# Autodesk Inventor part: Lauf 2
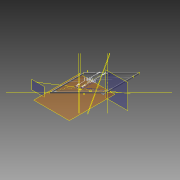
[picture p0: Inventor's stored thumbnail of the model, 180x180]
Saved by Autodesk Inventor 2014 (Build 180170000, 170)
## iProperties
Created: 2013-09
Part Number: Lauf 2
Material: Edelstahl
Document SubType Name: Modeling
Designer: Stefan Tammegger
Mass: 19399.1 g
Surface Area: 21755.4 cm^2
Volume: 2400.88 cm^3
Density: 8.08 g/cm^3
Appearance: Halbpoliert
Author: Stefan Tammegger
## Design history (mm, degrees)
node "Blöcke"
  sketch "FR 50 30 2"
    geometry: L1 (-39.377, 51.937)-(-65.377, 51.937); L2 (-67.377, 53.937)-(-67.377, 99.937); L3 (-65.377, 101.937)-(-39.377, 101.937); L4 (-37.377, 99.937)-(-37.377, 53.937); L5 (-39.377, 53.937)-(-65.377, 53.937); L6 (-65.377, 53.937)-(-65.377, 99.937); L7 (-65.377, 99.937)-(-39.377, 99.937); L8 (-39.377, 99.937)-(-39.377, 53.937); A1 r 2 centre (-39.377, 53.937) between (-39.377, 51.937) and (-37.377, 53.937); A2 r 2 centre (-39.377, 99.937) between (-37.377, 99.937) and (-39.377, 101.937); A3 r 2 centre (-65.377, 99.937) between (-65.377, 101.937) and (-67.377, 99.937); A4 r 2 centre (-65.377, 53.937) between (-67.377, 53.937) and (-65.377, 51.937); 4 further points
    constraints: 16 end point, 8 point on circle, 8 tangent, 6 point on line, 4 centre point, 4 parallel, 3 equal radius, 2 perpendicular, 1 horizontal, 1 midpoint, 3 other
    dimensions: "d1" = 30 distance of point (-67.377, 101.937) point (-37.377, 101.937); "d2" = 50 distance of point (-67.377, 51.937) point (-67.377, 101.937); "d3" = 2 distance between parallel lines of L2 L6; "d4" = 2 radius of A1
workplane "Arbeitsebene1"
sketch "Skizze1"
  geometry: L1 (-623.284, -302.67)-(-678.284, -302.67) reference; L2 (-678.284, -302.67)-(-678.284, -477.67) reference; L3 (501.716, 567.33)-(318.716, 567.33) reference; L4 (318.716, 567.33)-(318.716, 397.33) reference; L5 (-233.284, 47.33)-(-483.284, 47.33) reference; L6 (-483.284, 47.33)-(-483.284, -127.67) reference; L7 (318.716, 567.33)-(-483.284, 47.33); L8 (-358.284, 128.377)-(-358.284, 1168.377); 2 further points
  constraints: 4 end point, 1 coincident, 1 parallel, 1 point on line
  dimensions: "d0" = 1040 distance of L8.start L8.end
  node "Referenz1"
  node "Referenz2"
  node "Referenz3"
  node "Referenz4"
  node "Referenz5"
  node "Referenz6"
workplane "Arbeitsebene2"
  workpoint "Arbeitspunkt1"
  workaxis "Arbeitsachse1"
workpoint "Arbeitspunkt2"
workplane "Arbeitsebene3"
  workaxis "Arbeitsachse2"
  workpoint "Arbeitspunkt3"
sketch "Skizze4"
  geometry: 2 further points
  dimensions: "d12" = 20 dimension on point (140.706, 0)
extrude "Extrusion3" new body sketch "Skizze4" stored distance "d13" = 3000; taper "d14" = 0 deg
workplane "Arbeitsebene4"
sketch "Skizze5"
  geometry: L1 (-113.304, 75.845)-(-131.627, 75.845) reference; L2 (287.902, -17.155)-(287.902, 28.845) reference; 1 further point
  constraints: 1 horizontal, 1 vertical
extrude "Extrusion4" new body sketch "Skizze5" stored distance "d15" = 4000; taper "d16" = 0 deg
workplane "Arbeitsebene5"
sketch "Skizze6"
  geometry: L1 (-97, 0)-(-97, -165) reference; 1 further point
  dimensions: "d17" = 30 dimension on L1
extrude "Extrusion5" new body sketch "Skizze6" stored distance "d18" = 4000; taper "d19" = 0 deg
workplane "Arbeitsebene6"
feature "Trennen1"
workplane "Arbeitsebene7"
workplane "Arbeitsebene8"
feature "Trennen5"
feature "Trennen6"
workplane "Arbeitsebene9"
feature "Trennen7"
feature "Trennen8"
workplane "Arbeitsebene10"
sketch "Skizze7"
  geometry: L1 (318.716, 397.33)-(41.716, 397.33) reference; L2 (41.716, 397.33)-(41.716, 222.33) reference; L3 (41.716, 222.33)-(-233.284, 222.33) reference; L4 (-233.284, 222.33)-(-233.284, 47.33) reference; L5 (-233.284, 47.33)-(-483.284, 47.33) reference; L6 (-483.284, 47.33)-(-483.284, -127.67) reference; L7 (-483.284, -127.67)-(-623.284, -127.67) reference; L8 (-623.284, -127.67)-(-623.284, -302.67) reference; L9 (-623.284, -302.67)-(-678.284, -302.67) reference; L10 (-678.284, -302.67)-(-678.284, -477.67) reference; L11 (-678.284, -477.67)-(-733.284, -477.67) reference; L12 (318.716, 567.33)-(318.716, 397.33) reference; L13 (-233.284, 222.33)-(-233.284, 1262.33); 2 further points
  constraints: 2 end point, 1 coincident, 1 parallel
  dimensions: "d20" = 1040 distance of L3.end L13.end
  node "Referenz10"
  node "Referenz11"
  node "Referenz12"
  node "Referenz13"
  node "Referenz14"
  node "Referenz15"
  node "Referenz16"
  node "Referenz17"
  node "Referenz18"
  node "Referenz19"
  node "Referenz20"
  node "Referenz21"
workplane "Arbeitsebene11"
  workpoint "Arbeitspunkt4"
sketch "Skizze8"
  geometry: L1 (590.632, 60)-(-1024.704, 60) reference; 2 further points
  constraints: 1 horizontal
  dimensions: "d21" = 0 dimension on point (0, 0)
extrude "Extrusion7" new body sketch "Skizze8" stored distance "d24" = 4000; taper "d25" = 0 deg
workplane "Arbeitsebene12"
feature "Trennen9"
feature "Trennen10"
workplane "Arbeitsebene13"
feature "Trennen11"
feature "Trennen12"
sketch "Skizze9"
  geometry: L1 (0, 1478.165)-(0, 0) reference; L2 (2, 1478.997)-(2, -4.806) reference; L3 (2, 1478.997)-(2, -4.806) reference; L4 (-28, 1466.512)-(-28, 67.28) reference; L5 (-28, 1466.512)-(-28, 67.28) reference; L6 (0, 235.47)-(-80, 235.47); L7 (-80, 235.47)-(-80, 115.47); L8 (-80, 115.47)-(0, 115.47); L9 (0, 115.47)-(0, 235.47); L10 (-83, 265.47)-(-28, 265.47) reference; 1 further point
  constraints: 8 end point, 2 parallel, 1 collinear, 1 horizontal, 1 perpendicular
  dimensions: "d26" = 80 distance of L8.end L7.end; "d27" = 120 distance of L7.end L6.end; "d28" = 30 distance between parallel lines of L6 L10
  node "Projizierte Kontur1"
  node "Projizierte Kontur2"
  node "Referenz22"
workplane "Arbeitsebene14"
extrude "Extrusion8" new body sketch "Skizze9" stored distance "d29" = 4000; taper "d30" = 0 deg
hole "Bohrung1" diameter "d33" = 12; stored, may be unused: countersink angle "d37" = 90 deg, drill point angle "d39" = 118 deg; dims "d31" = 20, "d32" = 20, "d34" = 6, "d35" = 4, "d36" = 2, "d38" = 8
hole "Bohrung2" diameter "d42" = 12; stored, may be unused: countersink angle "d46" = 90 deg, drill point angle "d48" = 118 deg; dims "d40" = 20, "d41" = 20, "d43" = 6, "d44" = 4, "d45" = 2, "d47" = 8
sketch "Skizze10"
  geometry: L1 (0, 1478.165)-(0, 0) reference; L2 (-32, 87.662)-(151, 87.662) reference; L3 (120, 7.662)-(0, 7.662); L4 (0, 7.662)-(0, -112.338); L5 (0, -112.338)-(120, -112.338); L6 (120, -112.338)-(120, 7.662); L7 (1253, 834.779)-(-2, -13.84) reference; L8 (1203, -1155.529)-(28, 11.653) reference; L9 (1233, -1227.615)-(-2, -0.832) reference; L10 (28, 1410.885)-(28, 11.653) reference; 3 further points
  constraints: 8 end point, 2 parallel, 1 collinear, 1 horizontal, 1 perpendicular
  dimensions: "d49" = 120 distance of L5.end L4.end; "d50" = 120 distance of L4.end L3.end; "d51" = 80 distance between parallel lines of L3 L2
  node "Referenz23"
  node "Referenz24"
  node "Referenz25"
workplane "Arbeitsebene15"
extrude "Extrusion9" new body sketch "Skizze10" stored distance "d52" = 4000; taper "d53" = 0 deg
hole "Bohrung3" diameter "d56" = 12; stored, may be unused: countersink angle "d60" = 90 deg, drill point angle "d62" = 118 deg; dims "d54" = 20, "d55" = 20, "d57" = 6, "d58" = 4, "d59" = 2, "d61" = 8
hole "Bohrung4" diameter "d65" = 12; stored, may be unused: countersink angle "d69" = 90 deg, drill point angle "d71" = 118 deg; dims "d63" = 20, "d64" = 20, "d66" = 6, "d67" = 4, "d68" = 2, "d70" = 8
sketch "Skizze11" dims "d80" = 10
  geometry: L1 (-831.998, 12)-(-831.998, 58) reference; L2 (160.706, 58)-(160.706, 12) reference; L3 (-831.998, 12)-(160.706, 12) reference; L4 (-831.998, 58)-(160.706, 58) reference; L5 (-831.998, 35)-(160.706, 35); C1 r 2.5 at (-721.697, 35); C2 r 2.5 at (-611.397, 35); C3 r 2.5 at (-501.097, 35); C4 r 2.5 at (-390.797, 35); C5 r 2.5 at (-280.497, 35); C6 r 2.5 at (-170.197, 35); C7 r 2.5 at (-59.897, 35); C8 r 2.5 at (50.403, 35); 1 further point
  constraints: 8 centre point, 2 end point, 2 midpoint, 1 horizontal, 1 point on line, 14 other
  dimensions: "d72" = 992.70353 distance of L5.end L5.start (derived); "d73" = 5 diameter of C1; "d74" = 110.30039 distance from line of L1 C1.centre (= 0.111111 x d72); "d77" = 110.3 distance of C1.centre C2.centre
extrude "Extrusion10" new body sketch "Skizze11" stored distance "d82" = 4000; taper "d83" = 0 deg
sketch "Skizze12"
  geometry: 9 further points; 8 other entities
  constraints: 8 other
hole "Bohrung5" sketch "Skizze12" at (23, 197.76), (23, 353.229), (23, 508.699), (23, 664.169), (23, 819.638), (23, 975.108), (23, 1130.577), (23, 1286.047) diameter "d84" = 6; stored, may be unused: countersink angle "d88" = 90 deg, drill point angle "d90" = 118 deg; dims "d85" = 6, "d86" = 4, "d87" = 2, "d89" = 8
sketch "Skizze13"
  geometry: 9 further points; 8 other entities
  constraints: 8 other
hole "Bohrung6" sketch "Skizze13" at (23, 197.76), (23, 353.229), (23, 508.699), (23, 664.169), (23, 819.638), (23, 975.108), (23, 1130.577), (23, 1286.047) diameter "d91" = 6; stored, may be unused: countersink angle "d95" = 90 deg, drill point angle "d97" = 118 deg; dims "d92" = 6, "d93" = 4, "d94" = 2, "d96" = 8
workplane "Arbeitsebene16"
sketch "Skizze14"
  geometry: L1 (-861.998, 58)-(-861.998, 12) reference; L2 (-861.998, 12)-(190.706, 12) reference; L3 (190.706, 12)-(190.706, 58) reference; L4 (-861.998, 58)-(190.706, 58) reference; C1 r 5 at (-721.697, 35); 9 further points; 8 other entities
  constraints: 1 centre point, 1 coincident, 8 other
  dimensions: "d99" = 10 diameter of C1
extrude "Extrusion11" new body sketch "Skizze14" stored distance "d100" = 4000; taper "d101" = 0 deg
sketch "Skizze15"
  geometry: C1 r 5 at (0, 0) reference; 1 further point
hole "Bohrung7" sketch "Skizze15" at (0, 0) diameter "d102" = 6; stored, may be unused: countersink angle "d106" = 90 deg, drill point angle "d108" = 118 deg; dims "d103" = 6, "d104" = 4, "d105" = 2, "d107" = 8
workplane "Arbeitsebene17"
sketch "Skizze16"
  geometry: C1 r 5 at (-721.697, 35); 2 further points; 1 other entity
  constraints: 1 centre point, 1 coincident, 1 other
  dimensions: "d110" = 10 diameter of C1
extrude "Extrusion12" new body sketch "Skizze16" stored distance "d111" = 4000; taper "d112" = 0 deg
sketch "Skizze17"
  geometry: C1 r 5 at (0, 0) reference; 1 further point
hole "Bohrung8" sketch "Skizze17" at (0, 0) diameter "d113" = 6; stored, may be unused: countersink angle "d117" = 90 deg, drill point angle "d119" = 118 deg; dims "d114" = 6, "d115" = 4, "d116" = 2, "d118" = 8
pattern_linear "Rechteckige Anordnung1" dims "d122" = 155.47
node "Volumenkörper1"
node "Volumenkörper3"
node "Volumenkörper4"
node "Referenz8"
node "Referenz9"
node "Volumenkörper5"
node "Volumenkörper7"
node "Volumenkörper8"
node "Volumenkörper9"
node "Volumenkörper10"
node "Projizierte Kontur3"
node "Projizierte Kontur4"
node "Volumenkörper11"
node "Volumenkörper12"
node "FR 50 30 2:2" dims "d12" = 20
node "FR 50 30 2:3"
node "FR 50 30 2:4" dims "d17" = 30
node "FR 50 30 2:5" dims "d21" = 0
other parameters: "d98" = 38, "d109" = -1716
